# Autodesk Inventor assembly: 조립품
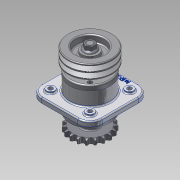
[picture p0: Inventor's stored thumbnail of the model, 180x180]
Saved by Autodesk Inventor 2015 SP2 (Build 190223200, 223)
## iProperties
Created: 2015-07
Part Number: 조립품
Document SubType Name: Assembly
Designer: AMC
Author: AMC
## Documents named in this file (12)
- C:\Users\AMC\Desktop\450735V1008\조립품.iam
- C:\Users\AMC\Desktop\450735V1008\본체.ipt
- C:\Users\AMC\Desktop\450735V1008\2-커버.ipt
- C:\Users\AMC\Desktop\450735V1008\3-축.ipt
- C:\Users\AMC\Desktop\450735V1008\4-V벨트풀리.ipt
- C:\Users\AMC\Desktop\450735V1008\5-체인 스프로킷.ipt
- C:\Users\AMC\Desktop\450735V1008\6-베어링 6206.ipt
- C:\Users\AMC\Desktop\450735V1008\7-부시.ipt
- C:\Users\AMC\Desktop\450735V1008\8-오일실 30x42.ipt
- C:\Users\AMC\Desktop\450735V1008\9-M16-너트.ipt
- C:\Users\AMC\Desktop\450735V1008\11-키 6x6.ipt
- C:\Users\AMC\Desktop\450735V1008\10-M6.ipt
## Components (22 placed, 10 different names)
1. 2-커버:1
2. 2-커버:2
3. 3-축:1
4. 4-V벨트풀리:1 — 각도:1
5. 5-체인 스프로킷:1 — 각도:2
6. 6-베어링 6206:1
7. 6-베어링 6206:2
8. 7-부시:1
9. 8-8-오일실 30x42:1
10. 8-8-오일실 30x42:2
11. 9-M16 너트:1
12. 9-M16 너트:2
13. 11-키 6x6:1 — 각도:1
14. 11-키 6x6:2 — 각도:2
15. 10-M6:1
16. 10-M6:2
17. 10-M6:3
18. 10-M6:4
19. 10-M6:5
20. 10-M6:6
21. 10-M6:7
22. 10-M6:8
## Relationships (2: Angle 2)
- 각도:1 [Angle]: 4-V벨트풀리:1 ↔ 11-키 6x6:1
- 각도:2 [Angle]: 5-체인 스프로킷:1 ↔ 11-키 6x6:2
